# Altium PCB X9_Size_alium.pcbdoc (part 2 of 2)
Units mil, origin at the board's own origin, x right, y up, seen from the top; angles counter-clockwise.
Board outline 3938 x 2560.05 mil, 2 copper layers (TOP, BOTTOM), stack 10.4 mil thick; 72 components, 121 nets, 447 pads, 520 vias.
Unrouted connection lines stored in the file: 78.
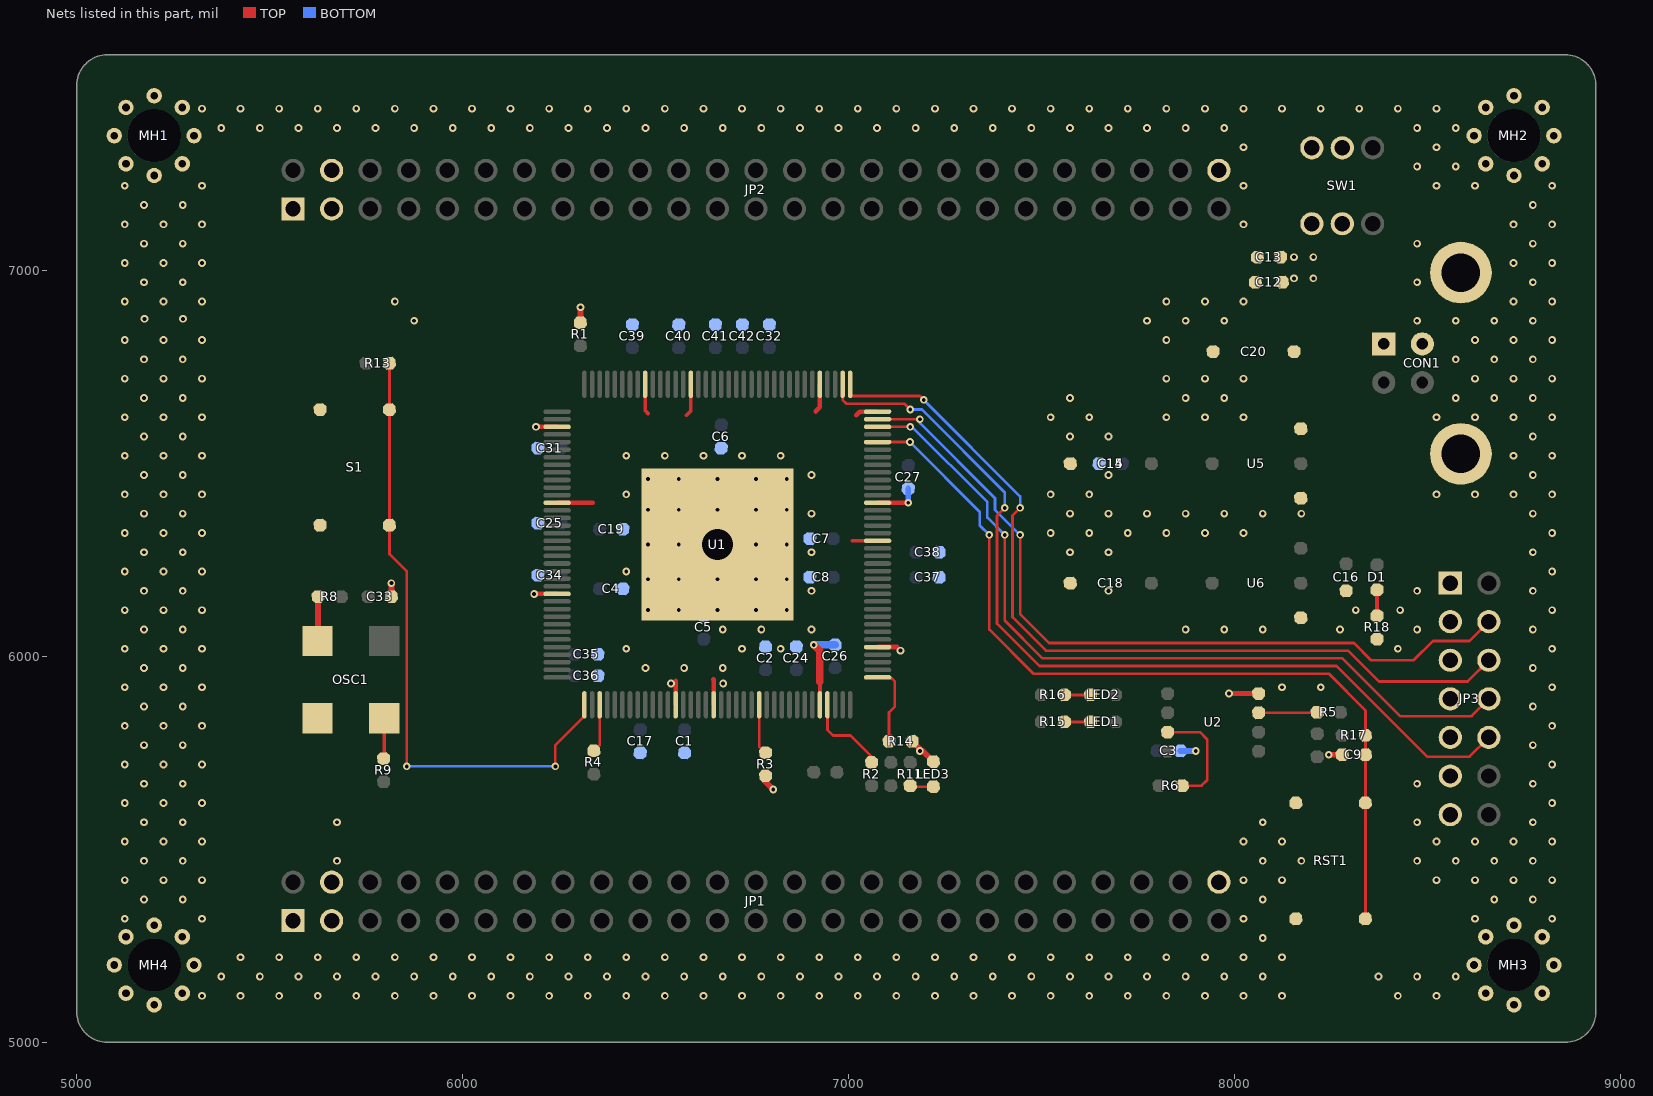
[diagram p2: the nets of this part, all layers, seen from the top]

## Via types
v1: diameter 20, hole 10, TOP to BOTTOM, 519 vias
v2: diameter 100, hole 80, TOP to BOTTOM, 1 vias

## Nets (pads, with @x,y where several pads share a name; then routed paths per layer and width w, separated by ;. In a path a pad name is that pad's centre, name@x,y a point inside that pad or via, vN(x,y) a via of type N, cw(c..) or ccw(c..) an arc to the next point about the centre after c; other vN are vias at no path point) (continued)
GND: C1.2 C2.2 C3.1 C4.1 C5.1 C6.1 C7.1 C8.1 C9.1 C12.1 C13.1 C14.1 C15.2 C16.1 C17.1 C18.2 C19.2 C20.2 C24.1 C25.1 C26.1 C27.1 C31.1 C32.1 C33.1 C34.1 C35.1 C36.1 C37.1 C38.1 C39.1 C40.1 C41.1 C42.1 CON1.4 CON1.5 CON1.6 JP1.3 JP1.4 JP1.50 JP2.3 JP2.4 JP2.50 JP3.1 JP3.3 JP3.5 JP3.7 JP3.9 JP3.11 JP3.13 LED3.K MH1.2 MH1.3 MH1.4 MH1.5 MH1.6 MH1.7 MH1.8 MH1.9 MH2.2 MH2.3 MH2.4 MH2.5 MH2.6 MH2.7 MH2.8 MH2.9 MH3.2 MH3.3 MH3.4 MH3.5 MH3.6 MH3.7 MH3.8 MH3.9 MH4.2 MH4.3 MH4.4 MH4.5 MH4.6 MH4.7 MH4.8 MH4.9 OSC1.2 R1.1 R3.2 R14.1 R18.1 RST1.3 RST1.4 S1.3 S1.4 U1.3 U1.13 U1.25 U1.49 U1.54 U1.68 U1.77 U1.91 U1.96 U1.108 U1.113 U1.130 U1.136 U1.EP U2.4 U5.1 U6.1 | length 1442.9
  TOP w10: U1.136@6473,6705.4 6473,6637 6480,6630 ; 6580,6625 6591.1,6636.1 U1.130@6591.1,6705.4 ; U1.68@6925.7,5874.6 6925.7,5934.3 ; 7010.2,6299.8 U1.91@7075.4,6299.8
  TOP w12: v1(6185,6162) U1.25@6244.6,6162 ; v1(6190,6595.1) U1.3@6244.6,6595.1 ; U1.13@6244.6,6398.3 6336.7,6398.3 ; U1.49@6551.7,5874.6 6551.7,5936.7 ; 6650,5940 6650.2,5939.8 U1.54@6650.2,5874.6 ; 6915,6635 6925.7,6645.7 U1.113@6925.7,6705.4 ; 7020,6625 7029.5,6634.5 U1.108@7075.4,6634.5 ; U1.77@7075.4,6024.3 7125.7,6024.3 v1(7135,6015) ; U1.96@7075.4,6398.3 v1(7155,6398.3)
  TOP w14: v1(7986.25,5903.75) U2.4@8063,5903.75
  TOP w15: C33.1@5815,6155 v1(5815,6190) ; R1.1@6305,6865 v1(6305,6905) ; R3.2@6785,5690 6785,5675 v1(6805,5655) ; R14.1@7165,5780 7185,5760 v1(7185,5755) 7192.5,5755 LED3.K@7220,5727.5 ; v1(8245,5745) C9.1@8280,5745
  TOP w20: v1(6910,6030) 6925.7,6014.3 6925.7,5934.3
  BOTTOM w15: v1(7155,6398.3) C27.1@7155,6435 ; C3.1@7860,5755 v1(7900,5755)
  BOTTOM w20: v1(6910,6030) C26.1@6965,6030
  other v1: 5324,5120 5424,5120 5524,5120 5624,5120 5724,5120 5824,5120 5924,5120 6024,5120 6124,5120 6224,5120 6324,5120 6424,5120 6524,5120 6624,5120 6724,5120 6824,5120 6924,5120 7024,5120 7124,5120 7224,5120 7324,5120 7424,5120 7524,5120 7624,5120 7724,5120 7824,5120 7924,5120 8024,5120 8124,5120 8424,5120 8524,5120 5374,5170 5474,5170 5574,5170 5674,5170 5774,5170 5874,5170 5974,5170 6074,5170 6174,5170 6274,5170 6374,5170 6474,5170 6574,5170 6674,5170 6774,5170 6874,5170 6974,5170 7074,5170 7174,5170 7274,5170 7374,5170 7474,5170 7574,5170 7674,5170 7774,5170 7874,5170 7974,5170 8074,5170 8374,5170 8474,5170 8574,5170 5424,5220 5524,5220 5624,5220 5724,5220 5824,5220 5924,5220 6024,5220 6124,5220 6224,5220 6324,5220 6424,5220 6524,5220 6624,5220 6724,5220 6824,5220 6924,5220 7024,5220 7124,5220 7224,5220 7324,5220 7424,5220 7524,5220 7624,5220 7724,5220 7824,5220 7924,5220 8024,5220 8124,5220 8074,5270 5124,5320 5324,5320 8024,5320 8624,5320 8824,5320 5174,5370 5274,5370 8074,5370 8674,5370 8774,5370 5124,5420 5224,5420 5324,5420 8024,5420 8124,5420 8524,5420 8624,5420 8724,5420 8824,5420 5174,5470 5274,5470 5674,5470 8074,5470 8174,5470 8474,5470 8574,5470 8674,5470 8774,5470 5124,5520 5224,5520 5324,5520 8024,5520 8124,5520 8524,5520 8624,5520 8724,5520 8824,5520 5174,5570 5274,5570 5674,5570 8074,5570 8474,5570 8774,5570 5124,5620 5224,5620 5324,5620 8824,5620 5174,5670 5274,5670 8474,5670 8774,5670 5124,5720 5224,5720 5324,5720 8824,5720 5174,5770 5274,5770 8774,5770 5124,5820 5224,5820 5324,5820 8824,5820 5174,5870 5274,5870 8774,5870 5124,5920 5224,5920 5324,5920 8124,5920 8224,5920 8824,5920 6540,5930 6675,5930 5174,5970 5274,5970 6474,5970 6574,5970 6674,5970 8774,5970 5124,6020 5224,6020 5324,6020 6424,6020 6724,6020 6824,6020 8424,6020 8824,6020 5174,6070 5274,6070 6674,6070 6774,6070 6904,6070 7874,6070 7974,6070 8074,6070 8274,6070 8474,6070 8774,6070 5124,6120 5224,6120 5324,6120 6480,6120 6560,6120 6660,6120 6760,6120 6840,6120 8315,6120 8430,6120 8824,6120 5174,6170 5274,6170 6904,6170 7674,6170 8474,6170 8774,6170 6480,6200 6560,6200 6660,6200 6760,6200 6840,6200 5124,6220 5224,6220 5324,6220 6424,6220 8824,6220 5174,6270 5274,6270 6904,6270 7574,6270 7674,6270 8774,6270 6480,6290 6560,6290 6760,6290 6840,6290 5124,6320 5224,6320 5324,6320 7524,6320 7624,6320 7724,6320 7824,6320 7924,6320 8024,6320 8824,6320 5174,6370 5274,6370 6904,6370 7574,6370 7674,6370 7774,6370 7874,6370 7974,6370 8074,6370 8174,6370 8774,6370 6480,6380 6560,6380 6660,6380 6760,6380 6840,6380 5124,6420 5224,6420 5324,6420 6424,6420 7524,6420 7624,6420 8524,6420 8624,6420 8724,6420 8824,6420 6480,6460 6560,6460 6660,6460 6760,6460 6840,6460 5174,6470 5274,6470 6904,6470 7674,6470 8774,6470 5124,6520 5224,6520 5324,6520 6424,6520 6524,6520 6624,6520 6724,6520 6824,6520 8724,6520 8824,6520 5174,6570 5274,6570 7574,6570 7674,6570 8774,6570 5124,6620 5224,6620 5324,6620 7524,6620 7624,6620 7824,6620 7924,6620 8024,6620 8524,6620 8624,6620 8724,6620 8824,6620 5174,6670 5274,6670 7574,6670 7874,6670 7974,6670 8574,6670 8674,6670 8774,6670 5124,6720 5224,6720 5324,6720 7824,6720 7924,6720 8024,6720 8624,6720 8724,6720 8824,6720 5174,6770 5274,6770 8574,6770 8674,6770 8774,6770 5124,6820 5224,6820 5324,6820 7824,6820 8624,6820 8724,6820 8824,6820 5874,6870 7774,6870 7874,6870 7974,6870 8474,6870 8574,6870 8674,6870 8774,6870 5175,6875 5275,6875 5124,6920 5224,6920 5324,6920 5824,6920 7824,6920 7924,6920 8024,6920 8724,6920 8824,6920 5174,6970 5274,6970 8474,6970 8774,6970 5124,7020 5224,7020 5324,7020 8724,7020 8824,7020 5174,7070 5274,7070 8474,7070 8774,7070 5124,7120 5224,7120 5324,7120 8024,7120 8724,7120 8824,7120 5174,7170 5274,7170 8774,7170 5124,7220 5324,7220 8024,7220 8524,7220 8624,7220 8824,7220 8474,7270 8574,7270 8024,7320 8524,7320 5374,7370 5474,7370 5574,7370 5674,7370 5774,7370 5874,7370 5974,7370 6074,7370 6174,7370 6274,7370 6374,7370 6474,7370 6574,7370 6674,7370 6774,7370 6874,7370 6974,7370 7074,7370 7174,7370 7274,7370 7374,7370 7474,7370 7574,7370 7674,7370 7774,7370 7874,7370 7974,7370 8474,7370 8574,7370 5324,7420 5424,7420 5524,7420 5624,7420 5724,7420 5824,7420 5924,7420 6024,7420 6124,7420 6224,7420 6324,7420 6424,7420 6524,7420 6624,7420 6724,7420 6824,7420 6924,7420 7024,7420 7124,7420 7224,7420 7324,7420 7424,7420 7524,7420 7624,7420 7724,7420 7824,7420 7924,7420 8024,7420 8124,7420 8224,7420 8324,7420 8424,7420 8524,7420
  other v2: 6660,6290
INT_B: R4.1 U1.39 | length 125.8
  TOP w7: R4.1@6340,5755 6354.9,5769.9 U1.39@6354.9,5874.6
M0: R2.1 U1.69 | length 223.4
  TOP w7: U1.69@6945.4,5874.6 6945.4,5809.6 6960,5795 7005,5795 7060,5740 R2.1@7060,5725
M1: R3.1 U1.60 | length 131.5
  TOP w7: U1.60@6768.3,5874.6 6768.3,5766.7 R3.1@6785,5750
NETCON1_1: CON1.1 SW1.2 SW1.5
NETD1_K: D1.K R18.2 | length 67.5
  TOP w10: R18.2@8370,6105 D1.K@8370,6172.5
NETLED1_K: LED1.K R15.2 | length 67.5
  TOP w7: R15.2@7560,5830 LED1.K@7627.5,5830
NETLED2_K: LED2.K R16.2 | length 67.5
  TOP w7: R16.2@7560,5900 LED2.K@7627.5,5900
NETLED3_A: LED3.A R11.1 | length 61
  TOP w7: R11.1@7160,5665 7162.5,5662.5 LED3.A@7220,5662.5
NETOSC1_1: OSC1.1 R8.1 | length 115.7
  TOP w15: OSC1.1@5623.4,6040 5625,6041.6 R8.1@5625,6155
NETOSC1_3: OSC1.3 R9.1 | length 105.7
  TOP w10: R9.1@5795,5735 5796.6,5736.6 OSC1.3@5796.6,5840
NETR5_2: R5.2 U2.3 | length 152.5
  TOP w7: U2.3@8063,5853.75 8213.75,5853.75 R5.2@8215,5855
NETR6_2: R6.2 U2.7 | length 287
  TOP w7: U2.7@7827,5803.75 7911.25,5803.75 7930,5785 7930,5680 7915,5665 R6.2@7865,5665
PROM_B: R13.2 S1.1 S1.2 U1.37 | length 1639.5
  TOP w7: R13.2@5810,6760 S1.1@5810,6640 S1.2@5810,6340 5810,6265 5855,6220 v1(5855,5715) ; v1(6240,5715) 6240,5770 6315.5,5845.5 U1.37@6315.5,5874.6
  BOTTOM w7: v1(5855,5715) v1(6240,5715)
RESET: C9.2 R17.2 RST1.1 RST1.2 U1.104 | length 2256.8
  TOP w7: U1.104@7075.4,6555.7 v1(7159.3,6555.7) ; v1(7365,6315) 7365,6070 7480,5955 8245,5955 8340,5860 R17.2@8340,5795 C9.2@8340,5745 RST1.1@8340,5620 RST1.2@8340,5320
  BOTTOM w7: v1(7159.3,6555.7) 7340,6375 7340,6340 v1(7365,6315)
SUSPEND: R14.2 U1.73 | length 210.2
  TOP w7: U1.73@7075.4,5945.5 7109.5,5945.5 7120,5935 7120,5870 7105,5855 R14.2@7105,5780
TCK: JP3.6 U1.109 | length 2223.8
  TOP w7: U1.109@7004.5,6705.4 7004.5,6680.5 7010,6675 7185,6675 v1(7195,6665) ; v1(7445,6385) 7425,6365 7425,6101.71 7511.71,6015 8295,6015 8375,5935 8605,5935 JP3.6@8660,5990
  BOTTOM w7: v1(7195,6665) 7445,6415 v1(7445,6385)
TDI: JP3.10 U1.110 | length 2346.8
  TOP w7: U1.110@6984.8,6705.4 6984.8,6665.2 6995,6655 7145,6655 v1(7160,6640) ; v1(7405,6385) 7385,6365 7385,6085 7495,5975 8265,5975 8500,5740 8610,5740 JP3.10@8660,5790
  BOTTOM w7: v1(7160,6640) 7190,6640 7405,6425 v1(7405,6385)
TDO: JP3.8 U1.106 | length 2067.2
  TOP w7: U1.106@7075.4,6595.1 v1(7160,6595.1) ; v1(7405,6315) 7405,6093.42 7503.42,5995 8280,5995 8430,5845 8615,5845 JP3.8@8660,5890
  BOTTOM w7: v1(7160,6595.1) 7164.9,6595.1 7360,6400 7360,6360 v1(7405,6315)
TMS: JP3.4 U1.107 | length 2028.2
  TOP w7: U1.107@7075.4,6614.8 v1(7185,6614.8) ; v1(7445,6315) 7445,6110 7520,6035 8310,6035 8355,5990 8465,5990 8515,6040 8610,6040 JP3.4@8660,6090
  BOTTOM w7: v1(7185,6614.8) 7185,6605 7380,6410 7380,6380 v1(7445,6315)
VCC_5V: C12.2 C13.2 C20.1 JP1.1 JP2.1 SW1.3 SW1.6 U5.3
  other v1: 8155,6980 8205,6980 8155,7035 8205,7035
pads on no net: CON1.2 CON1.3 JP3.12 JP3.14 MH1.1 MH2.1 MH3.1 MH4.1 SW1.1 SW1.4 U1.72 U1.75 U1.123

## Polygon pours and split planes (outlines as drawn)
GND on TOP "TOP-GND" (solid, pour order 1000): 6325,5930 6325,6042.87 6325,6044.92 6325,6075 6385,6075 6385,6355 6325,6355 6325,6559.07 6325,6560.93 6325,6650 6605.48,6650 6605.48,6600.5 6605.58,6598.32 6605.86,6596.16 6606.33,6594.02 6606.99,6591.94 6607.82,6589.93 6608.83,6587.99 6610,6586.15 6611.33,6584.42 6612.81,6582.81 6614.42,6581.33 6616.15,6580 6617.99,6578.83 6619.93,6577.82 6621.94,6576.99 6624.02,6576.33 6626.16,6575.86 6628.32,6575.58 6630.5,6575.48 6632.68,6575.58 6634.84,6575.86 6636.98,6576.33 6639.06,6576.99 6641.07,6577.82 6643.01,6578.83 6644.85,6580 6646.58,6581.33 6648.19,6582.81 6649.67,6584.42 6651,6586.15 6652.17,6587.99 6653.18,6589.93 6654.01,6591.94 6654.67,6594.02 6655.14,6596.16 6655.42,6598.32 6655.52,6600.5 6655.52,6650 6973.82,6650 6987.33,6636.48 7020,6636.48 7020,6285.52 6960,6285.52 6957.82,6285.42 6955.66,6285.14 6953.52,6284.67 6951.44,6284.01 6949.43,6283.18 6947.49,6282.17 6945.65,6281 6943.92,6279.67 6942.31,6278.19 6940.83,6276.58 6939.5,6274.85 6938.33,6273.01 6937.32,6271.07 6936.49,6269.06 6935.83,6266.98 6935.36,6264.84 6935.08,6262.68 6934.98,6260.5 6935.08,6258.32 6935.36,6256.16 6935.83,6254.02 6936.49,6251.94 6937.32,6249.93 6938.33,6247.99 6939.5,6246.15 6940.83,6244.42 6942.31,6242.81 6943.92,6241.33 6945.65,6240 6947.49,6238.83 6949.43,6237.82 6951.44,6236.99 6953.52,6236.33 6955.66,6235.86 6957.82,6235.58 6960,6235.48 7020,6235.48 7020,6014.72 7009.75,6004.47 7009.2,6004.34 7007.1,6003.74 7005.06,6002.96 7003.1,6002 7001.23,6000.88 6999.46,5999.6 6997.81,5998.17 6996.29,5996.6 6994.92,5994.91 6993.69,5993.1 6992.63,5991.19 6991.74,5989.2 6991.03,5987.14 6990.5,5985.02 6990.15,5982.86 6990,5980.69 6990,5979.06 6990,5930 6640,5930 6640,6020 6640,6040 6605,6075 6580,6075 6560,6055 6560,6035 6585,6010 6585,5930 6325,5930
GND on TOP "TOP-GND 1" (solid, pour order 1001): 7980,5936.48 8237.33,5936.48 8246.9,5926.9 8246.9,5896.9 8235.02,5885.02 8228,5885.02 8202,5885.02 8201.11,5885 7980,5885 7970,5895 7970,5926.48 7980,5936.48
GND on TOP "TOP-GND 2" (solid, pour order 1002): 5078.74,5000 5071.88,5000.3 5065.07,5001.2 5058.36,5002.68 5051.81,5004.75 5045.46,5007.38 5039.37,5010.55 5033.58,5014.24 5028.13,5018.42 5023.06,5023.06 5018.42,5028.13 5014.24,5033.58 5010.55,5039.37 5007.38,5045.46 5004.75,5051.81 5002.68,5058.36 5001.2,5065.07 5000.3,5071.88 5000,5078.74 5000,7480.31 5000.3,7487.17 5001.2,7493.98 5002.68,7500.69 5004.75,7507.24 5007.38,7513.59 5010.55,7519.68 5014.24,7525.47 5018.42,7530.92 5023.06,7535.99 5028.13,7540.63 5033.58,7544.81 5039.37,7548.5 5045.46,7551.67 5051.81,7554.3 5058.36,7556.37 5065.07,7557.85 5071.88,7558.75 5078.74,7559.05 8858.26,7559.05 8865.12,7558.75 8871.93,7557.85 8878.64,7556.37 8885.19,7554.3 8891.54,7551.67 8897.63,7548.5 8903.42,7544.81 8908.87,7540.63 8913.94,7535.99 8918.58,7530.92 8922.76,7525.47 8926.45,7519.68 8929.62,7513.59 8932.25,7507.24 8934.32,7500.69 8935.8,7493.98 8936.7,7487.17 8937,7480.31 8937,5078.74 8936.7,5071.88 8935.8,5065.07 8934.32,5058.36 8932.25,5051.81 8929.62,5045.46 8926.45,5039.37 8922.76,5033.58 8918.58,5028.13 8913.94,5023.06 8908.87,5018.42 8903.42,5014.24 8897.63,5010.55 8891.54,5007.38 8885.19,5004.75 8878.64,5002.68 8871.93,5001.2 8865.12,5000.3 8858.26,5000 5078.74,5000
NETCON1_1 on TOP "TOP-NETCON1_1" (solid, pour order 1003): 8250,7360 8260,7370 8305,7370 8315,7360 8315,6985 8425,6875 8425,6770 8415,6760 8280,6760 8250,6790 8250,7360
VCC_5V on TOP "TOP-VCC_5V" (solid, pour order 1004): 8100,6915 8100,7355 8115,7370 8215,7370 8225,7360 8225,6760 8280,6705 8280,6575 8265,6560 8100,6560 8085,6575 8085,6900 8100,6915
FPGA_3V3 on TOP "TOP-FPGA_3V3" (solid, pour order 1005): 8450,6220 8260,6220 8235,6245 8120,6245 8110,6255 8110,6325 8120,6335 8230,6335 8245,6350 8245,6455 8230,6470 8090,6470 8045,6425 7720,6425 7710,6435 7710,6565 7720,6575 8015,6575 8055,6535 8380,6535 8395,6520 8395,6395 8445,6345 8680,6345 8700,6325 8700,6165 8690,6155 8640,6155 8625,6170 8625,6240 8615,6250 8480,6250 8450,6220
FPGA_3V3 on TOP "TOP-FPGA_3V3 1" (solid, pour order 1006): 5430,7310 5595,7310 5600,7305 5600,7230 5585,7215 5515,7215 5495,7195 5495,7105 5765,6835 5765,6795 5765,6740 5755,6730 5625,6730 5605,6750 5605,6825 5595,6835 5365,7065 5365,7245 5430,7310
FPGA_1V2 on TOP "TOP-FPGA_1V2" (solid, pour order 1007): 7700,6260 7715,6275 8045,6275 8100,6220 8215,6220 8225,6210 8225,6165 8215,6155 8095,6155 8045,6105 7710,6105 7700,6115 7700,6260
GND on BOTTOM "BOTTOM-GND" (solid, pour order 1008): 5078.74,5000 5071.88,5000.3 5065.07,5001.2 5058.36,5002.68 5051.81,5004.75 5045.46,5007.38 5039.37,5010.55 5033.58,5014.24 5028.13,5018.42 5023.06,5023.06 5018.42,5028.13 5014.24,5033.58 5010.55,5039.37 5007.38,5045.46 5004.75,5051.81 5002.68,5058.36 5001.2,5065.07 5000.3,5071.88 5000,5078.74 5000,7480.31 5000.3,7487.17 5001.2,7493.98 5002.68,7500.69 5004.75,7507.24 5007.38,7513.59 5010.55,7519.68 5014.24,7525.47 5018.42,7530.92 5023.06,7535.99 5028.13,7540.63 5033.58,7544.81 5039.37,7548.5 5045.46,7551.67 5051.81,7554.3 5058.36,7556.37 5065.07,7557.85 5071.88,7558.75 5078.74,7559.05 8858.26,7559.05 8865.12,7558.75 8871.93,7557.85 8878.64,7556.37 8885.19,7554.3 8891.54,7551.67 8897.63,7548.5 8903.42,7544.81 8908.87,7540.63 8913.94,7535.99 8918.58,7530.92 8922.76,7525.47 8926.45,7519.68 8929.62,7513.59 8932.25,7507.24 8934.32,7500.69 8935.8,7493.98 8936.7,7487.17 8937,7480.31 8937,5078.74 8936.7,5071.88 8935.8,5065.07 8934.32,5058.36 8932.25,5051.81 8929.62,5045.46 8926.45,5039.37 8922.76,5033.58 8918.58,5028.13 8913.94,5023.06 8908.87,5018.42 8903.42,5014.24 8897.63,5010.55 8891.54,5007.38 8885.19,5004.75 8878.64,5002.68 8871.93,5001.2 8865.12,5000.3 8858.26,5000 5078.74,5000
VCC_5V on BOTTOM "BOTTOM-VCC_5V" (solid, pour order 1009): 8085,7125 8085,7350 8105,7370 8215,7370 8225,7360 8235,7350 8235,7080 8225,7070 8225,6980 8210,6965 5520,6965 5480,6925 5480,5365 5500,5345 5590,5345 5605,5330 5605,5255 5595,5245 5405,5245 5365,5285 5365,7145 5410,7190 5575,7190 5590,7175 5590,7105 5605,7090 8050,7090 8085,7125
FPGA_3V3 on BOTTOM "BOTTOM-FPGA_3V3" (solid, pour order 1010): 5535,5385 5520,5400 5520,6735 5520,6925 5535,6940 5755,6940 5765,6930 5765,6795 5765,6025 5775,6015 6200,6015 6235,6050 6235,6775 6280,6820 7060,6820 7085,6845 7745,6845 7795,6795 7795,6430 7790,6425 7705,6425 7690,6440 7690,6625 7605,6710 7140,6710 7120,6690 7120,6565 7170,6515 7170,6480 7165,6475 7115,6475 7105,6465 7105,6340 7120,6325 7185,6325 7190,6320 7190,6185 7185,6180 7060,6180 7040,6200 7040,6640 7010,6670 6340,6670 6310,6640 6310,6630 6310,5930 6340,5900 6700,5900 6745,5945 6745,5975 6760,5990 6790,5990 7350,5990 7470,5870 8310,5870 8320,5860 8320,5815 8305,5800 7835,5800 7820,5785 7820,5705 7810,5695 7480,5695 7315,5860 6955,5860 6890,5795 5775,5795 5740,5795 5605,5660 5605,5625 5605,5400 5590,5385 5535,5385
FPGA_1V2 on BOTTOM "BOTTOM-FPGA_1V2" (solid, pour order 1011): 7675,6145 7690,6160 7835,6160 7840,6155 7840,6090 7835,6085 6960,6085 6940,6105 6940,6545 6905,6580 6405,6580 6375,6550 6375,6135 6380,6130 6440,6130 6505,6065 6525,6065 6635,6065 6645,6055 6645,6030 6640,6025 6510,6025 6475,6025 6410,6090 6350,6090 6335,6105 6335,6575 6385,6625 6920,6625 6990,6555 6990,6165 7010,6145 7675,6145
no net on Top Overlay (solid): 5139.6,6628.8 5207.6,6667.2 5139.6,6705.6 5139.6,6732.8 5228.4,6680 5322,6736.8 5322,6709.6 5249.2,6667.2 5322,6624.8 5322,6598.4 5228.4,6654.4 5139.6,6602.4 5139.6,6628.8
no net on Top Overlay (solid): 5139.6,6284.8 5139.6,6308 5301.2,6308 5301.2,6382.4 5322,6382.4 5322,6284.8 5139.6,6284.8
no net on Top Overlay (solid): 5322,6399.2 5322,6422.4 5139.6,6422.4 5139.6,6399.2 5322,6399.2
no net on Top Overlay (solid): 5139.6,6451.2 5139.6,6472.8 5277.2,6564 5139.6,6564 5139.6,6587.2 5322,6587.2 5322,6565.6 5182.8,6474.4 5184.4,6474.4 5322,6475.2 5322,6472.8 5322,6451.2 5139.6,6451.2
no net on Top Overlay (solid): 5139.6,6113.6 5207.6,6152 5139.6,6190.4 5139.6,6217.6 5228.4,6164.8 5322,6221.6 5322,6194.4 5249.2,6152 5322,6109.6 5322,6083.2 5228.4,6139.2 5139.6,6087.2 5139.6,6113.6
no net on Top Overlay (solid): 5322,6232.8 5322,6256 5139.6,6256 5139.6,6232.8 5322,6232.8
no net on Top Overlay (solid): 5139.6,5877.6 5185.2,5832 5186.8,5833.6 5230.8,5871.2 5276.4,5832 5322,5872 5322,6011.2 5275.6,5970.4 5320.4,5931.2 5320.4,5930.4 5318.8,5928.8 5276.4,5892 5230.8,5931.2 5230,5931.2 5185.2,5892 5141.2,5930.4 5142.8,5932 5186,5969.6 5186,5970.4 5184.4,5972 5139.6,6010.4 5139.6,5877.6
no net on Top Solder (solid): 5065,5125 5065,5060 5135,5060 5135,5125 5065,5125
no net on Top Solder (solid): 9045,6505 8870,6505 8850,6485 8850,5175 8760,5085 5180,5085 5090,5175 5090,7395 5170,7475 8765,7475 8850,7390 8850,7055 8865,7040 8990,7040 9000,7050 9000,7560 8905,7655 5055,7655 4910,7510 4910,5080 5055,4935 8990,4935 9060,5005 9060,6485 9045,6500 9045,6505

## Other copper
TOP:
  pour cut-out: 5605.04,5315 5604.97,5317.36 5604.79,5319.71 5604.48,5322.05 5604.05,5324.36 5603.5,5326.66 5602.83,5328.92 5602.04,5331.14 5601.14,5333.32 5600.13,5335.45 5599,5337.52 5597.77,5339.53 5596.43,5341.47 5595,5343.34 5593.47,5345.13 5591.84,5346.84 5590.13,5348.47 5588.34,5350 5586.47,5351.43 5584.53,5352.77 5582.52,5354 5580.45,5355.13 5578.32,5356.14 5576.14,5357.04 5573.92,5357.83 5571.66,5358.5 5569.36,5359.05 5567.05,5359.48 5564.71,5359.79 5562.36,5359.97 5560,5360.04 5557.64,5359.97 5555.29,5359.79 5552.95,5359.48 5550.64,5359.05 5548.34,5358.5 5546.08,5357.83 5543.86,5357.04 5541.68,5356.14 5539.55,5355.13 5537.48,5354 5535.47,5352.77 5533.53,5351.43 5531.66,5350 5529.87,5348.47 5528.16,5346.84 5526.53,5345.13 5525,5343.34 5523.57,5341.47 5522.23,5339.53 5521,5337.52 5519.87,5335.45 5518.86,5333.32 5517.96,5331.14 5517.17,5328.92 5516.5,5326.66 5515.95,5324.36 5515.52,5322.05 5515.21,5319.71 5515.03,5317.36 5514.96,5315 5515.03,5312.64 5515.21,5310.29 5515.52,5307.95 5515.95,5305.64 5516.5,5303.34 5517.17,5301.08 5517.96,5298.86 5518.86,5296.68 5519.87,5294.55 5521,5292.48 5522.23,5290.47 5523.57,5288.53 5525,5286.66 5526.53,5284.87 5528.16,5283.16 5529.87,5281.53 5531.66,5280 5533.53,5278.57 5535.47,5277.23 5537.48,5276 5539.55,5274.87 5541.68,5273.86 5543.86,5272.96 5546.08,5272.17 5548.34,5271.5 5550.64,5270.95 5552.95,5270.52 5555.29,5270.21 5557.64,5270.03 5560,5269.96 5562.36,5270.03 5564.71,5270.21 5567.05,5270.52 5569.36,5270.95 5571.66,5271.5 5573.92,5272.17 5576.14,5272.96 5578.32,5273.86 5580.45,5274.87 5582.52,5276 5584.53,5277.23 5586.47,5278.57 5588.34,5280 5590.13,5281.53 5591.84,5283.16 5593.47,5284.87 5595,5286.66 5596.43,5288.53 5597.77,5290.47 5599,5292.48 5600.13,5294.55 5601.14,5296.68 5602.04,5298.86 5602.83,5301.08 5603.5,5303.34 5604.05,5305.64 5604.48,5307.95 5604.79,5310.29 5604.97,5312.64 5605.04,5315
  pour cut-out: 5605.04,5415 5604.97,5417.36 5604.79,5419.71 5604.48,5422.05 5604.05,5424.36 5603.5,5426.66 5602.83,5428.92 5602.04,5431.14 5601.14,5433.32 5600.13,5435.45 5599,5437.52 5597.77,5439.53 5596.43,5441.47 5595,5443.34 5593.47,5445.13 5591.84,5446.84 5590.13,5448.47 5588.34,5450 5586.47,5451.43 5584.53,5452.77 5582.52,5454 5580.45,5455.13 5578.32,5456.14 5576.14,5457.04 5573.92,5457.83 5571.66,5458.5 5569.36,5459.05 5567.05,5459.48 5564.71,5459.79 5562.36,5459.97 5560,5460.04 5557.64,5459.97 5555.29,5459.79 5552.95,5459.48 5550.64,5459.05 5548.34,5458.5 5546.08,5457.83 5543.86,5457.04 5541.68,5456.14 5539.55,5455.13 5537.48,5454 5535.47,5452.77 5533.53,5451.43 5531.66,5450 5529.87,5448.47 5528.16,5446.84 5526.53,5445.13 5525,5443.34 5523.57,5441.47 5522.23,5439.53 5521,5437.52 5519.87,5435.45 5518.86,5433.32 5517.96,5431.14 5517.17,5428.92 5516.5,5426.66 5515.95,5424.36 5515.52,5422.05 5515.21,5419.71 5515.03,5417.36 5514.96,5415 5515.03,5412.64 5515.21,5410.29 5515.52,5407.95 5515.95,5405.64 5516.5,5403.34 5517.17,5401.08 5517.96,5398.86 5518.86,5396.68 5519.87,5394.55 5521,5392.48 5522.23,5390.47 5523.57,5388.53 5525,5386.66 5526.53,5384.87 5528.16,5383.16 5529.87,5381.53 5531.66,5380 5533.53,5378.57 5535.47,5377.23 5537.48,5376 5539.55,5374.87 5541.68,5373.86 5543.86,5372.96 5546.08,5372.17 5548.34,5371.5 5550.64,5370.95 5552.95,5370.52 5555.29,5370.21 5557.64,5370.03 5560,5369.96 5562.36,5370.03 5564.71,5370.21 5567.05,5370.52 5569.36,5370.95 5571.66,5371.5 5573.92,5372.17 5576.14,5372.96 5578.32,5373.86 5580.45,5374.87 5582.52,5376 5584.53,5377.23 5586.47,5378.57 5588.34,5380 5590.13,5381.53 5591.84,5383.16 5593.47,5384.87 5595,5386.66 5596.43,5388.53 5597.77,5390.47 5599,5392.48 5600.13,5394.55 5601.14,5396.68 5602.04,5398.86 5602.83,5401.08 5603.5,5403.34 5604.05,5405.64 5604.48,5407.95 5604.79,5410.29 5604.97,5412.64 5605.04,5415
  pour cut-out: 170 vertices and 0 holes, not listed, extent 8636.21,7261.21 8813.79,7438.79
  pour cut-out: 170 vertices and 0 holes, not listed, extent 8636.21,5111.21 8813.79,5288.79
  pour cut-out: 170 vertices and 0 holes, not listed, extent 5111.21,7261.21 5288.79,7438.79
  pour cut-out: 170 vertices and 0 holes, not listed, extent 5111.21,5111.21 5288.79,5288.79
  pour cut-out: 173 vertices and 0 holes, not listed, extent 5340,5100 8730,7390
  text "POWER" at 8440,7115 h60
  text "CONFIG" at 5960,6375 h60 r90
  text "JTAG" at 8395,5270 h60
  text "RST" at 8182.5,5150 h60
BOTTOM:
  drawing of 113 lines, arcs and shapes, not listed

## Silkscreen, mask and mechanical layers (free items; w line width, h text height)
Top Overlay:
  drawing of 400 lines, arcs and shapes, not listed
  text "142" at 6235,7442.5 h45 r270
  text "140" at 6335,7442.5 h45 r270
  text "138" at 6435,7442.5 h45 r270
  text "134" at 6535,7442.5 h45 r270
  text "132" at 6635,7442.5 h45 r270
  text "127" at 6735,7442.5 h45 r270
  text "124" at 6835,7442.5 h45 r270
  text "120" at 6935,7442.5 h45 r270
  text "118" at 7035,7442.5 h45 r270
  text "116" at 7135,7442.5 h45 r270
  text "114" at 7235,7442.5 h45 r270
  text "111" at 7335,7442.5 h45 r270
  text "102" at 7435,7442.5 h45 r270
  text "100" at 7535,7442.5 h45 r270
  text "3V3" at 5535,7432.5 h45 r270
  text "GND" at 5635,7432.5 h45 r270
  text "GND" at 7935,7432.5 h45 r270
  text "98" at 7635,7425 h45 r270
  text "95" at 7735,7425 h45 r270
  text "93" at 7835,7425 h45 r270
  text "11" at 5735,7415 h45 r270
  text "9" at 5835,7397.5 h45 r270
  text "7" at 5935,7397.5 h45 r270
  text "5" at 6035,7397.5 h45 r270
  text "1" at 6135,7397.5 h45 r270
  text "GND" at 5635,7092.5 h45 r270
  text "143" at 6235,7092.5 h45 r270
  text "141" at 6335,7092.5 h45 r270
  text "139" at 6435,7092.5 h45 r270
  text "137" at 6535,7092.5 h45 r270
  text "133" at 6635,7092.5 h45 r270
  text "131" at 6735,7092.5 h45 r270
  text "126" at 6835,7092.5 h45 r270
  text "121" at 6935,7092.5 h45 r270
  text "119" at 7045,7092.5 h45 r270
  text "117" at 7140,7092.5 h45 r270
  text "115" at 7235,7092.5 h45 r270
  text "112" at 7335,7092.5 h45 r270
  text "105" at 7435,7092.5 h45 r270
  text "101" at 7535,7092.5 h45 r270
  text "5V" at 5535,7075 h45 r270
  text "12" at 5735,7075 h45 r270
  text "10" at 5835,7075 h45 r270
  text "99" at 7645,7065 h45 r270
  text "97" at 7735,7065 h45 r270
  text "94" at 7845,7065 h45 r270
  text "92" at 7935,7065 h45 r270
  text "8" at 5935,7057.5 h45 r270
  text "6" at 6035,7057.5 h45 r270
  text "2" at 6135,7057.5 h45 r270
  text "SPARTAN-6" at 5532,5673.5 h156 r90
  text "3V3" at 5535,5582.5 h45 r270
  text "GND" at 5635,5582.5 h45 r270
  text "GND" at 7935,5582.5 h45 r270
  text "15" at 5735,5565 h45 r270
  text "17" at 5835,5565 h45 r270
  text "22" at 5935,5565 h45 r270
  text "24" at 6035,5565 h45 r270
  text "27" at 6135,5565 h45 r270
  text "30" at 6235,5565 h45 r270
  text "33" at 6335,5565 h45 r270
  text "35" at 6435,5565 h45 r270
  text "41" at 6535,5565 h45 r270
  text "44" at 6635,5565 h45 r270
  text "46" at 6735,5565 h45 r270
  text "48" at 6835,5565 h45 r270
  text "51" at 6935,5565 h45 r270
  text "57" at 7035,5565 h45 r270
  text "59" at 7135,5565 h45 r270
  text "62" at 7235,5565 h45 r270
  text "67" at 7335,5565 h45 r270
  text "78" at 7435,5565 h45 r270
  text "80" at 7535,5565 h45 r270
  text "82" at 7635,5565 h45 r270
  text "84" at 7735,5565 h45 r270
  text "87" at 7835,5565 h45 r270
  text "GND" at 5635,5242.5 h45 r270
  text "5V" at 5535,5225 h45 r270
  text "14" at 5735,5225 h45 r270
  text "16" at 5835,5225 h45 r270
  text "21" at 5935,5225 h45 r270
  text "23" at 6035,5225 h45 r270
  text "26" at 6135,5225 h45 r270
  text "29" at 6235,5225 h45 r270
  text "32" at 6335,5225 h45 r270
  text "34" at 6435,5225 h45 r270
  text "40" at 6535,5225 h45 r270
  text "43" at 6635,5225 h45 r270
  text "45" at 6735,5225 h45 r270
  text "47" at 6835,5225 h45 r270
  text "50" at 6935,5225 h45 r270
  text "56" at 7035,5225 h45 r270
  text "58" at 7135,5225 h45 r270
  text "61" at 7235,5225 h45 r270
  text "66" at 7335,5225 h45 r270
  text "74" at 7435,5225 h45 r270
  text "79" at 7535,5225 h45 r270
  text "81" at 7635,5225 h45 r270
  text "83" at 7735,5225 h45 r270
  text "85" at 7835,5225 h45 r270
  text "88" at 7935,5225 h45 r270
Bottom Overlay:
  lines w10: 5520,5500 8110,5500 ; 6975,5665 6975,5870 7540,5870 7590,5870 7590,5665 6975,5665
  text "OMDAZZ" at 7550,5716.67 h100
  text "https://www.aliexpress.com/store/2274002" at 8117.5,5528.33 h80
Top Solder:
  lines w80: 8535,7515 8845,7515 8890,7470 8890,7075 ; 8580,7515 5075,7515 5045,7485 5045,5085 5085,5045 8850,5045 8890,5085 8890,6475
  text "POWER" at 8440,7115 h60
  text "CONFIG" at 5960,6375 h60 r90
  text "JTAG" at 8395,5270 h60
  text "RST" at 8182.5,5150 h60
OUTLINE:
  lines w1: 5000,5078.74 ccw(c5078.74,5078.74) 5078.74,5000 8858.26,5000 ccw(c8858.26,5078.74) 8937,5078.74 8937,7480.31 ccw(c8858.26,7480.31) 8858.26,7559.05 5078.74,7559.05 ccw(c5078.74,7480.31) 5000,7480.31 5000,5078.74
DRAWING_ORIGIN:
  lines w1: 4975,5000 5025,5000 ; 5000,4975 5000,5025
DIMENSION:
  lines w1: 5000,4895 5001,4895.1 ; 5000,4895 5001,4894.9 ; 5000,4895 7490,4895 ; 5000,4895 5001,4895.1 ; 5000,4895 5001,4894.9 ; 5000,4895 7490,4895 ; 5001,4894.9 5001,4895.1 ; 5001,4894.9 5001,4895.1 ; 7490,4895 8937,4895 ; 7490,4895 8937,4895 ; 8936,4894.9 8937,4895 ; 8936,4894.9 8936,4895.1 ; 8936,4894.9 8937,4895 ; 8936,4894.9 8936,4895.1 ; 8936,4895.1 8937,4895 ; 8936,4895.1 8937,4895 ; 9139.9,5001 9140,5000 ; 9139.9,5001 9140.1,5001 ; 9139.9,5001 9140,5000 ; 9139.9,5001 9140.1,5001 ; 9139.9,7558.05 9140,7559.05 ; 9139.9,7558.05 9140.1,7558.05 ; 9139.9,7558.05 9140,7559.05 ; 9139.9,7558.05 9140.1,7558.05 ; 9140,5000 9140.1,5001 ; 9140,5000 9140,5935 ; 9140,5000 9140.1,5001 ; 9140,5000 9140,5935 ; 9140,5935 9140,7559.05 ; 9140,5935 9140,7559.05 ; 9140,7559.05 9140.1,7558.05 ; 9140,7559.05 9140.1,7558.05 ; 5000,4894.7 5000,5078.44 5000,4894.7 ; 8835.3,5000 9140.3,5000 8835.3,5000 ; 8858.56,7559.05 9140.3,7559.05 8858.56,7559.05 ; 8937,4894.7 8937,5078.44 8937,4894.7
  text "65" at 9124.5,5908 h35 r90
  text "65" at 9124.5,5908 h35 r90
  text "100" at 7447.5,4910.5 h35
  text "100" at 7447.5,4910.5 h35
